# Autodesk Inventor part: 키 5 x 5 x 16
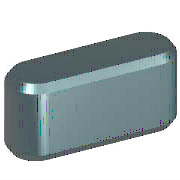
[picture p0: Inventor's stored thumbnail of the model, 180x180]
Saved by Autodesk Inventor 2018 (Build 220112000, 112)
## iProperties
IsCustomPart: 1
Created: 2012-02
Part Number: 키 5 x 5 x 16
Material: 강철, 연강
Description: 키 및 해당 키홈
Document SubType Name: Modeling
Standard: KS B 1311
Designer: mduedu
Standards Organization: KS
Language: ko-KR
Size Designation: 5 x 5 x 16
Categories: <MemberInstance><Categories><Category DisplayName="샤프트 부품" InternalName="7f7aeb1f-a693-4053-b835-cee3144e0d98" Mnemonic="SHFT"><Category DisplayName="키" Interna
Density: 1 g/cm^3
Appearance: 노란색
Author: mduedu
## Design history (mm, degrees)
workplane "Work Plane1"
workplane "Work Plane2"
sketch "스케치1"
  geometry: L1 (2.5, 2.5)-(11.5, 2.5); L2 (11.5, -2.5)-(2.5, -2.5); L3 (0, 8.9)-(0, -4.4) reference; L4 (-3.2, 0)-(19.2, 0) reference; L5 (14, 0)-(14, 7); A1 r 2.5 centre (2.5, 0) between (2.5, 2.5) and (2.5, -2.5); A2 r 2.5 centre (11.5, 0) between (11.5, -2.5) and (11.5, 2.5)
  constraints: 6 end point, 5 point on circle, 4 tangent, 3 point on line, 2 centre point, 1 horizontal, 1 parallel, 1 perpendicular
  dimensions: "d0" = 2.5 radius of A1 (= 0.5 x PB); "d13" = 2.5 radius of A2 (= 0.5 x PB); "d14" = 14 distance between parallel lines of L5 L3 (= NLG)
extrude "본체1" new body sketch "스케치1" taper "d3" = 0 deg; stored distance "d4" = 10
workplane "Work Plane3"
body "Solid1"
chamfer "모따기1" distance "d8" = 0.4 (= PHH); stored, may be unused: second distance "d9" = 0.4 (= PHH), angle "d15" = 45 deg
other parameters: "d1" = -3 (= -PNT), "d2" = 2 (= PH - PNT), "NLG" = 14 [user parameter; used in 3 equation terms], "PB" = 5 [user parameter; used in 2 equation terms], "PNT" = 3 [user parameter; used in 2 equation terms], "PH" = 5 [user parameter; used in 1 equation term], "PHH" = 0.4 [user parameter; used in 2 equation terms], "d10" = 0, "d16" = 0, "d17" = 0, "d18" = 0, "WDMIN" = 12 [user parameter], "PLB2" = 14 (= NLG) [user parameter], "WDMAX" = 17 [user parameter], "PLB1" = 14 (= NLG) [user parameter], "RR" = 0.16 [user parameter], "PUEB" = 2.3 [user parameter]
